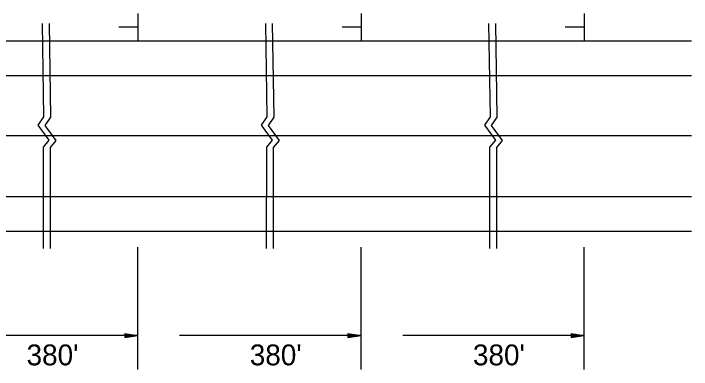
# Model space of a CAD drawing. Extents: x 1806907 to 1812607, y 675071 to 676228.
# Drawn here: x 1810091.1 to 1810285.9, y 675311.3 to 675413.7 of the extents above; entities that cross this region are included whole.
import ezdxf

# ---------------------------------------------------------------- set-up
doc = ezdxf.new("R2010")
doc.units = 0
doc.layers.add('Default', color=7, linetype='Continuous')

msp = doc.modelspace()

# ---------------------------------------------------------------- linework, layer by layer
at = {"layer": 'Default'}
for p, q in [((1810126.8, 675413.69), (1810126.8, 675405.86)), ((1810190.96, 675413.69), (1810190.96, 675405.86)), ((1810255.13, 675413.69), (1810255.13, 675405.86)), ((1810126.69, 675409.8), (1810121.35, 675409.8)), ((1810190.85, 675409.8), (1810185.51, 675409.8)), ((1810255.01, 675409.8), (1810249.67, 675409.8)), ((1809377.42, 675405.86), (1810285.94, 675405.86)), ((1809932.92, 675395.86), (1810285.94, 675395.86)), ((1810285.94, 675378.48), (1809843.73, 675378.48)), ((1809932.92, 675361.1), (1810285.94, 675361.1)), ((1809377.42, 675351.1), (1810285.94, 675351.1)), ((1810126.8, 675311.31), (1810126.8, 675346.52)), ((1810190.96, 675311.31), (1810190.96, 675346.52)), ((1810255.13, 675311.31), (1810255.13, 675346.52)), ((1810123.05, 675321.66), (1810126.8, 675321.1)), ((1810123.05, 675321.66), (1810123.05, 675320.54)), ((1810123.05, 675321.57), (1810126.18, 675321.1)), ((1810187.21, 675321.66), (1810190.96, 675321.1)), ((1810187.21, 675321.66), (1810187.21, 675320.54)), ((1810187.21, 675321.57), (1810190.34, 675321.1)), ((1810251.38, 675321.66), (1810255.13, 675321.1)), ((1810251.38, 675321.66), (1810251.38, 675320.54)), ((1810251.38, 675321.57), (1810254.5, 675321.1)), ((1810126.8, 675321.1), (1810074.62, 675321.1)), ((1810123.05, 675321.47), (1810125.53, 675321.1)), ((1810123.05, 675321.38), (1810124.91, 675321.1)), ((1810123.05, 675321.28), (1810124.27, 675321.1)), ((1810123.05, 675321.19), (1810123.65, 675321.1)), ((1810123.05, 675320.54), (1810126.8, 675321.1)), ((1810123.05, 675320.91), (1810124.27, 675321.1)), ((1810123.05, 675320.72), (1810125.53, 675321.1)), ((1810123.05, 675320.63), (1810126.18, 675321.1)), ((1810123.05, 675320.82), (1810124.91, 675321.1)), ((1810123.05, 675321.01), (1810123.65, 675321.1)), ((1810190.96, 675321.1), (1810138.78, 675321.1)), ((1810187.21, 675321.47), (1810189.69, 675321.1)), ((1810187.21, 675321.38), (1810189.07, 675321.1)), ((1810187.21, 675321.28), (1810188.43, 675321.1)), ((1810187.21, 675321.19), (1810187.81, 675321.1)), ((1810187.21, 675320.54), (1810190.96, 675321.1)), ((1810187.21, 675320.91), (1810188.43, 675321.1)), ((1810187.21, 675320.72), (1810189.69, 675321.1)), ((1810187.21, 675320.63), (1810190.34, 675321.1)), ((1810187.21, 675320.82), (1810189.07, 675321.1)), ((1810187.21, 675321.01), (1810187.81, 675321.1)), ((1810255.13, 675321.1), (1810202.94, 675321.1)), ((1810251.38, 675321.47), (1810253.85, 675321.1)), ((1810251.38, 675321.38), (1810253.23, 675321.1)), ((1810251.38, 675321.28), (1810252.59, 675321.1)), ((1810251.38, 675321.19), (1810251.97, 675321.1)), ((1810251.38, 675320.54), (1810255.13, 675321.1)), ((1810251.38, 675320.91), (1810252.59, 675321.1)), ((1810251.38, 675320.72), (1810253.85, 675321.1)), ((1810251.38, 675320.63), (1810254.5, 675321.1)), ((1810251.38, 675320.82), (1810253.23, 675321.1)), ((1810251.38, 675321.01), (1810251.97, 675321.1))]:
    msp.add_line(p, q, dxfattribs=at)
for points in [[(1810099.31, 675410.87), (1810099.71, 675383.99), (1810098.09, 675381.58), (1810101.25, 675377.25), (1810099.59, 675375.25), (1810099.58, 675346.1)], [(1810101.3, 675410.87), (1810101.71, 675383.91), (1810100.09, 675381.5), (1810103.25, 675377.17), (1810101.59, 675375.17), (1810101.58, 675346.1)], [(1810163.47, 675410.87), (1810163.87, 675383.99), (1810162.25, 675381.58), (1810165.41, 675377.25), (1810163.75, 675375.25), (1810163.74, 675346.1)], [(1810165.46, 675410.87), (1810165.87, 675383.91), (1810164.25, 675381.5), (1810167.41, 675377.17), (1810165.75, 675375.17), (1810165.74, 675346.1)], [(1810227.63, 675410.87), (1810228.04, 675383.99), (1810226.41, 675381.58), (1810229.58, 675377.25), (1810227.91, 675375.25), (1810227.9, 675346.1)], [(1810229.62, 675410.87), (1810230.03, 675383.91), (1810228.41, 675381.5), (1810231.57, 675377.17), (1810229.91, 675375.17), (1810229.9, 675346.1)]]:
    msp.add_lwpolyline(points, dxfattribs=at)

# ---------------------------------------------------------------- texts
for p in [(1810094.82, 675312.49), (1810158.98, 675312.49), (1810223.14, 675312.49)]:
    msp.add_text("380'", height=6, dxfattribs=at).set_placement(p)

doc.saveas('drawing.dxf')
